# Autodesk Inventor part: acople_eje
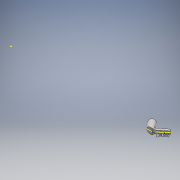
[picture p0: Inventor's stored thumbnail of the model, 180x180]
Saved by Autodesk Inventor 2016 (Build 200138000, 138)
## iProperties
Created: 2017-06
Part Number: acople_eje
Material: Generic
Document SubType Name: Modeling
Designer: laboratorioesan
Density: 1 g/cm^3
Appearance: Default
Author: laboratorioesan
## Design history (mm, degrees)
sketch "Sketch1"
  geometry: L1 (655, 44.5)-(655, -44.5) reference; L2 (743.516, -4.5)-(540.972, -4.5) reference; L3 (540.972, 29.5)-(743.516, 29.5) reference; L4 (743.516, 29.5)-(743.516, -4.5) reference; L5 (675, -19.5)-(775, -19.5) reference; L6 (575, -19.5)-(675, -19.5) reference; L7 (362.5, -19.5)-(575, -19.5) reference; L8 (752.654, 65)-(520.832, 65) reference; L9 (79, 173.396)-(79, 144.26) reference; L10 (705, 0.351)-(264, 544.26); L11 (705, 0.351)-(743.389, 32.387); L12 (743.389, 32.387)-(749.796, 24.71); L13 (749.796, 24.71)-(696.819, -19.5); L14 (696.819, -19.5)-(690.412, -11.822); L15 (690.412, -11.822)-(705, 0.351); 1 further point
  constraints: 12 end point, 1 collinear, 1 parallel, 1 perpendicular, 1 point on line
  dimensions: "d0" = 185 horizontal distance of L10.end L9.end; "d1" = 400 vertical distance of L10.end L9.end; "d3" = 50 distance from line of L1 L10.start; "d5" = 50 distance of L10.start L11.end; "d8" = 10 distance of L11.end L12.end; "d9" = 69 distance of L12.end L13.end; "d10" = 10 distance of L13.end L14.end
extrude "Extrusion1" new body sketch "Sketch1" stored distance "d11" = 15; taper "d12" = 0 deg
sketch "Sketch2"
  geometry: L1 (0, 0)-(0, 15) reference; L2 (69, 0)-(0, 0) reference; L3 (69, 0)-(69, 15) reference; L4 (0, 15)-(69, 15) reference; C1 r 3.5 at (61, 7.5); 1 further point
  constraints: 1 centre point
  dimensions: "d13" = 7 diameter of C1; "d14" = 8 distance from line of L3 C1.centre
extrude "Extrusion2" cut sketch "Sketch2" distance "d15" = 15; taper "d16" = 0 deg
sketch "Sketch3"
  geometry: L1 (0, 0)-(0, 15) reference; L2 (69, 0)-(0, 0) reference; L3 (69, 0)-(69, 15) reference; L4 (0, 15)-(69, 15) reference; C1 r 3.5 at (61, 7.5) reference; C2 r 15 at (0, 7.5); 1 further point
  constraints: 1 centre point, 1 midpoint
  dimensions: "d17" = 30 diameter of C2
extrude "Extrusion3" join sketch "Sketch3" distance "d19" = 10; taper "d20" = 0 deg
sketch "Sketch4"
  geometry: L1 (0, 0)-(-56.01, 0) reference; L2 (0, 0)-(0, 15) reference; L3 (-56.01, 15)-(0, 15) reference; C1 r 3.5 at (-8, 7.5) reference; C2 r 15 at (-69, 7.5); C3 r 9 at (-69, 7.5); A1 r 15 centre (-69, 7.5) between (-56.01, 15) and (-56.01, 0) reference; A2 r 15 centre (-69, 7.5) between (-56.01, 15) and (-56.01, 0) reference; 1 further point
  constraints: 2 centre point, 2 coincident
  dimensions: "d21" = 18 diameter of C3
extrude "Extrusion4" join sketch "Sketch4" distance "d22" = 30; taper "d23" = 0 deg
fillet "Fillet1" dims "d24" = 7.5
sketch "Sketch5"
  geometry: L1 (705.403, -12.337)-(694.191, 1.1) reference; L2 (705.403, -12.337)-(705.403, -12.337) reference; L3 (694.191, 1.1)-(705.403, -12.337) reference; L4 (694.191, 1.1)-(694.191, 1.1) reference; L5 (682.707, 20.822)-(659.674, 1.6) reference; L6 (675, -19.5)-(775, -19.5) reference; L7 (704.352, -16.5)-(664.734, -16.5); L8 (664.734, -16.5)-(664.734, -29.056); L9 (664.734, -29.056)-(704.352, -29.056); L10 (704.352, -29.056)-(704.352, -16.5); 1 further point
  constraints: 8 end point, 2 parallel, 1 horizontal, 1 perpendicular
  dimensions: "d25" = 3 distance between parallel lines of L6 L7
extrude "Extrusion5" cut sketch "Sketch5" stored distance "d26" = 60; taper "d27" = 0 deg
sketch "Sketch6"
  geometry: L1 (-7.301, 5.263)-(-7.301, -5.263) reference; A1 r 9 centre (0, 0) between (-7.301, -5.263) and (-7.301, 5.263) reference; A2 r 9 centre (0, 0) between (-7.301, 5.263) and (-7.301, -5.263) reference; 1 further point
extrude "Extrusion6" join sketch "Sketch6" distance "d28" = 10; taper "d29" = 0 deg
sketch "Sketch7"
  geometry: C1 r 9 at (0, 0) reference; C2 r 15 at (0, 0) reference; 1 further point
extrude "Extrusion7" join sketch "Sketch7" distance "d30" = 15; taper "d31" = 0 deg
sketch "Sketch8"
  geometry: C1 r 9 at (0, 0) reference; C2 r 15 at (0, 0) reference; C3 r 9.125 at (0, 0); 1 further point
  constraints: 1 centre point, 1 coincident
  dimensions: "d32" = 18.25 diameter of C3
extrude "Extrusion8" cut sketch "Sketch8" stored distance "d33" = 15; taper "d34" = 0 deg
sketch "Sketch9"
  geometry: L1 (-15.607, 8.988)-(-15.607, 19.513) reference; L2 (0, 28.501)-(0, 0) reference; 3 further points; 2 other entities
  constraints: 2 other
extrude "Extrusion9" cut sketch "Sketch9" distance "d35" = 100; taper "d36" = 0 deg
sketch "Sketch10"
  geometry: L1 (709.695, -8.755)-(749.796, 24.71) reference; L2 (700.414, -16.5)-(674.779, -16.5) reference; 1 further point
  dimensions: "d37" = 39.8456 deg angle of L2 L1 (derived)
body "Solid1"
node "Reference1"
node "Reference2"
node "Reference3"
node "Reference4"
node "Reference5"
node "Reference6"
node "Reference7"
node "Reference8"
node "Reference9"
node "Projected Loop1"
node "Projected Loop2"
node "Projected Loop3"
node "Projected Loop4"
node "Reference10"
node "Projected Loop5"
node "Projected Loop6"
node "Projected Loop7"
node "Projected Loop8"
